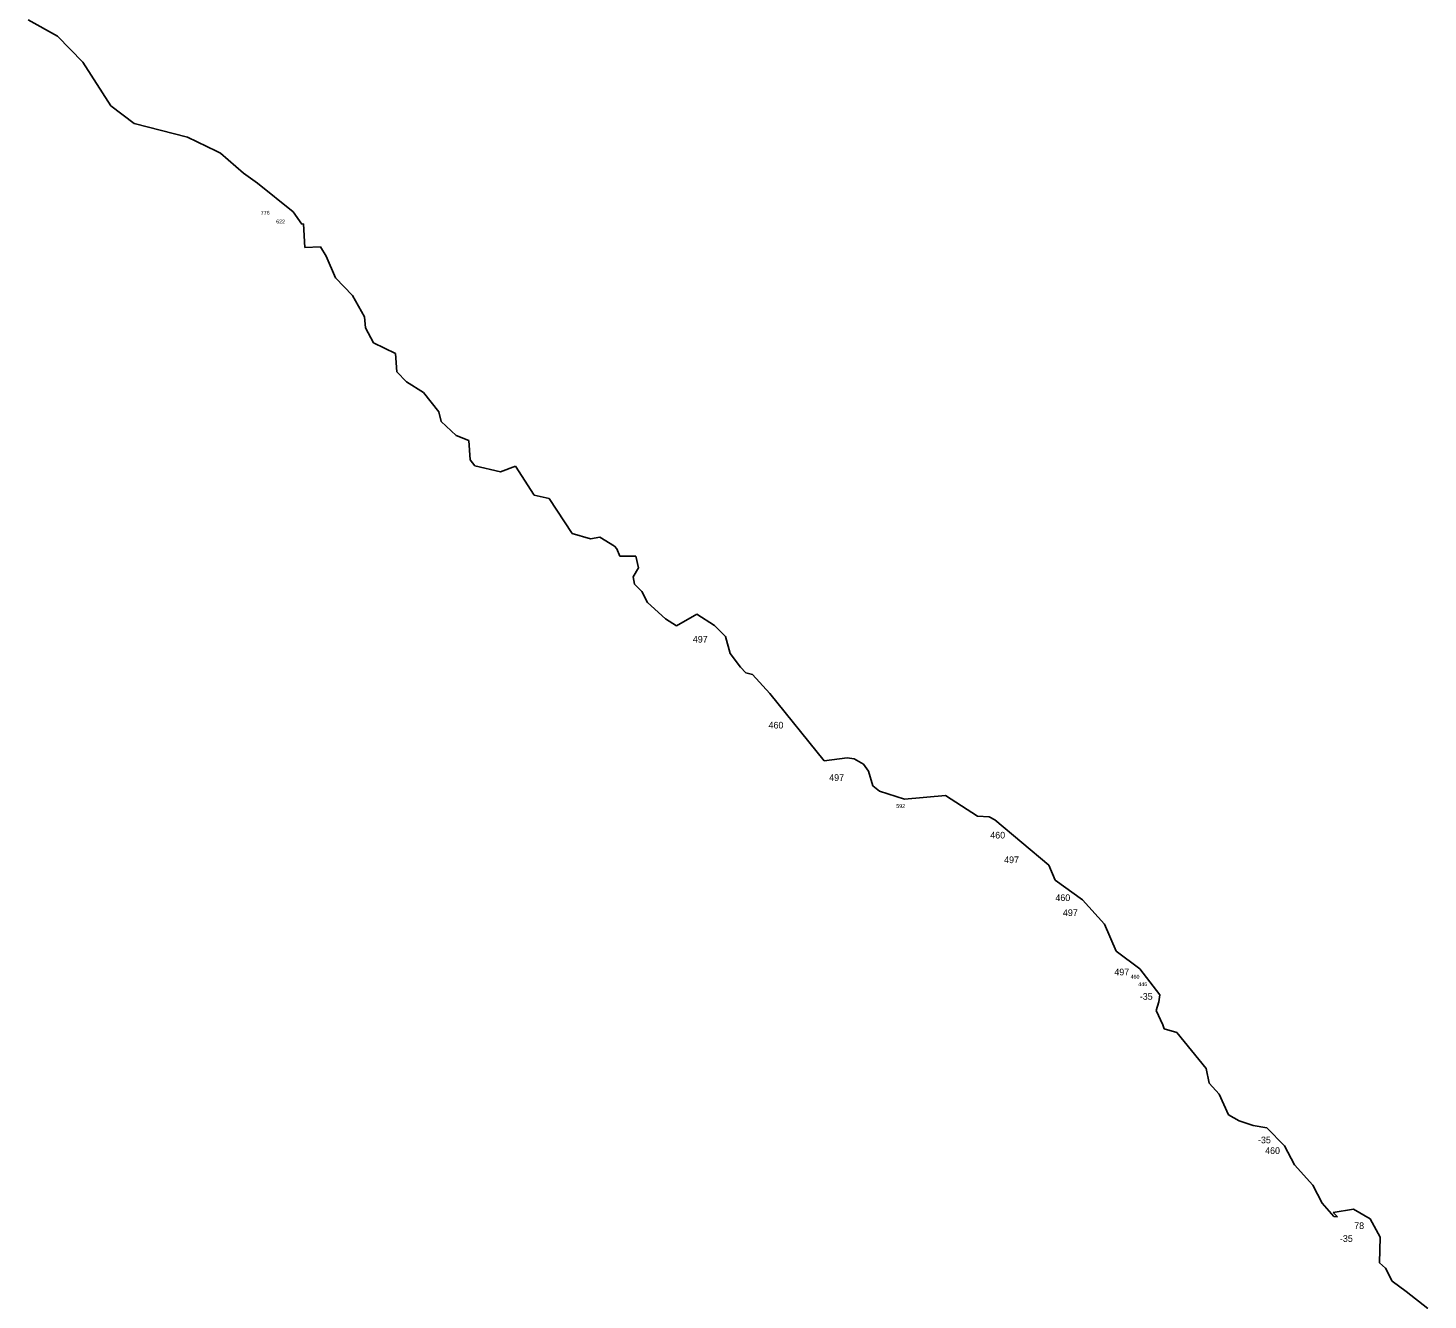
# Model space of a CAD drawing. Extents: x -782977 to -778030, y -975420 to -964838.
# Drawn here: x -779818 to -778366, y -967487 to -966168 of the extents above; entities that cross this region are included whole.
import ezdxf

# ---------------------------------------------------------------- set-up
doc = ezdxf.new("R2010")
doc.units = 0
doc.layers.add('Vrstva 13', color=7, linetype='Continuous')
doc.layers.add('Vrstva 24', color=7, linetype='Continuous')

msp = doc.modelspace()

# ---------------------------------------------------------------- linework, layer by layer
at = {"layer": 'Vrstva 13'}
for p, q in [((-779818.04, -966159.18), (-779787.3, -966176.21)), ((-779787.3, -966176.21), (-779761.3, -966203.24)), ((-779761.3, -966203.24), (-779732.23, -966248.32)), ((-779732.23, -966248.32), (-779707.81, -966266.62)), ((-779707.81, -966266.62), (-779652.48, -966280.84)), ((-779652.48, -966280.84), (-779622.47, -966295.41)), ((-779622.47, -966295.41), (-779618.41, -966297.63)), ((-779618.41, -966297.63), (-779594.6, -966318.31)), ((-779594.6, -966318.31), (-779580.07, -966328.54)), ((-779580.07, -966328.54), (-779543.08, -966358.28)), ((-779543.08, -966358.28), (-779534.09, -966371.21)), ((-779534.09, -966371.21), (-779532.11, -966370.7)), ((-779532.11, -966370.7), (-779530.87, -966395.46)), ((-779530.87, -966395.46), (-779514.66, -966394.59)), ((-779514.66, -966394.59), (-779508.52, -966404.45)), ((-779508.52, -966404.45), (-779499.02, -966426.88)), ((-779499.02, -966426.88), (-779481.49, -966445.22)), ((-779481.49, -966445.22), (-779468.78, -966467.14)), ((-779468.78, -966467.14), (-779467.76, -966478.72)), ((-779467.76, -966478.72), (-779459.43, -966494.18)), ((-779459.43, -966494.18), (-779436.64, -966505.14)), ((-779436.64, -966505.14), (-779435.25, -966524.35)), ((-779435.25, -966524.35), (-779425.39, -966534.65)), ((-779425.39, -966534.65), (-779407.86, -966545.68)), ((-779407.86, -966545.68), (-779391.64, -966565.85)), ((-779391.64, -966565.85), (-779389.3, -966575.94)), ((-779389.3, -966575.94), (-779373.96, -966590.48)), ((-779373.96, -966590.48), (-779360.74, -966595.37)), ((-779360.74, -966595.37), (-779359.28, -966615.68)), ((-779359.28, -966615.68), (-779354.31, -966621.67)), ((-779354.31, -966621.67), (-779327.87, -966628.1)), ((-779327.87, -966628.1), (-779312.09, -966622.11)), ((-779312.09, -966622.11), (-779292.96, -966652.07)), ((-779292.96, -966652.07), (-779277.47, -966655.72)), ((-779277.47, -966655.72), (-779253.37, -966692.03)), ((-779253.37, -966692.03), (-779234.31, -966697.51)), ((-779234.31, -966697.51), (-779224.88, -966695.61)), ((-779224.88, -966695.61), (-779209.4, -966705.12)), ((-779209.4, -966705.12), (-779206.99, -966707.82)), ((-779206.99, -966707.82), (-779203.93, -966715.42)), ((-779203.93, -966715.42), (-779187.35, -966715.42)), ((-779187.35, -966715.42), (-779184.5, -966727.62)), ((-779184.5, -966727.62), (-779190.11, -966736.83)), ((-779190.11, -966736.83), (-779188.95, -966744.43)), ((-779188.95, -966744.43), (-779181.2, -966751.96)), ((-779181.2, -966751.96), (-779175.29, -966763.5)), ((-779175.29, -966763.5), (-779156.74, -966780.38)), ((-779145.24, -966787.65), (-779124.16, -966775.64)), ((-779124.16, -966775.64), (-779105.9, -966787.25)), ((-779156.74, -966780.38), (-779145.24, -966787.65)), ((-779105.9, -966787.25), (-779094.51, -966798.72)), ((-779094.51, -966798.72), (-779089.47, -966816.26)), ((-779089.47, -966816.26), (-779078.66, -966830.58)), ((-779078.66, -966830.58), (-779073.4, -966836.35)), ((-779073.4, -966836.35), (-779066.46, -966838.32)), ((-779066.46, -966838.32), (-779048.33, -966857.77)), ((-779048.33, -966857.77), (-778991.94, -966927.92)), ((-778991.94, -966927.92), (-778968.06, -966924.48)), ((-778960.83, -966925.58), (-778968.06, -966924.48)), ((-778951.06, -966931.24), (-778960.83, -966925.58)), ((-778945.93, -966938.59), (-778951.06, -966931.24)), ((-778941.54, -966953.78), (-778945.93, -966938.59)), ((-778934.53, -966959.34), (-778941.54, -966953.78)), ((-778908.82, -966967.38), (-778934.53, -966959.34)), ((-778908.82, -966967.38), (-778866.02, -966963.57)), ((-778866.02, -966963.57), (-778833.07, -966985.12)), ((-778833.07, -966985.12), (-778820.72, -966985.93)), ((-778820.72, -966985.93), (-778815.02, -966988.86)), ((-778815.02, -966988.86), (-778758.93, -967036.06)), ((-778758.93, -967036.06), (-778752.5, -967051.69)), ((-778752.5, -967051.69), (-778724.15, -967072.01)), ((-778724.15, -967072.01), (-778701.22, -967097.28)), ((-778701.22, -967097.28), (-778689.1, -967125.05)), ((-778689.1, -967125.05), (-778664.56, -967143.32)), ((-778664.56, -967143.32), (-778643.73, -967170.35)), ((-778644.83, -967177.66), (-778647.46, -967186.87)), ((-778643.73, -967170.35), (-778644.83, -967177.66)), ((-778647.46, -967186.87), (-778640.52, -967201.71)), ((-778640.52, -967201.71), (-778639.29, -967205.87)), ((-778639.29, -967205.87), (-778626.21, -967209.6)), ((-778626.21, -967209.6), (-778595.68, -967246.79)), ((-778595.68, -967246.79), (-778592.57, -967262.17)), ((-778592.57, -967262.17), (-778582.24, -967273.46)), ((-778582.24, -967273.46), (-778572.34, -967295.06)), ((-778572.34, -967295.06), (-778561.56, -967301.09)), ((-778561.56, -967301.09), (-778546.81, -967305.84)), ((-778546.81, -967305.84), (-778532.86, -967308.47)), ((-778532.86, -967308.47), (-778514.38, -967326.96)), ((-778514.38, -967326.96), (-778504, -967346.68)), ((-778504, -967346.68), (-778485.02, -967367.88)), ((-778485.02, -967367.88), (-778475.16, -967386.59)), ((-778475.16, -967386.59), (-778463.25, -967400.47)), ((-778442.94, -967392.86), (-778463.83, -967396.08)), ((-778463.83, -967396.08), (-778459.45, -967400.61)), ((-778459.45, -967400.61), (-778463.25, -967400.47)), ((-778425.7, -967402.66), (-778442.94, -967392.86)), ((-778415.33, -967421.8), (-778425.7, -967402.66)), ((-778415.92, -967448.4), (-778415.33, -967421.8)), ((-778409.5, -967454.03), (-778415.92, -967448.4)), ((-778402.71, -967467.54), (-778409.5, -967454.03)), ((-778388.18, -967478.07), (-778402.71, -967467.54)), ((-778365.53, -967495.83), (-778388.18, -967478.07))]:
    msp.add_line(p, q, dxfattribs=at)

# ---------------------------------------------------------------- texts
at = {"layer": 'Vrstva 24'}
for s, height, p in [('776', 4, (-779576.545, -966361.33)), ('622', 4, (-779560.544, -966370.37)), ('497', 6.912, (-779128.268, -966805.122)), ('460', 6.912, (-779049.734, -966894.212)), ('497', 6.912, (-778986.798, -966948.572)), ('592', 4, (-778917.224, -966976.64)), ('460', 6.912, (-778819.684, -967008.302)), ('497', 6.912, (-778805.308, -967033.852)), ('460', 6.912, (-778752.114, -967073.192)), ('497', 6.912, (-778744.298, -967088.702)), ('497', 6.912, (-778690.958, -967150.242)), ('460', 4, (-778674.123, -967153.68)), ('446', 4, (-778666.093, -967161.41)), ('-35', 6.912, (-778664.546, -967175.575)), ('-35', 6.912, (-778541.936, -967324.405)), ('460', 6.912, (-778534.524, -967335.532)), ('78', 6.912, (-778442.103, -967413.392)), ('-35', 6.912, (-778456.926, -967426.665))]:
    msp.add_text(s, height=height, dxfattribs=at).set_placement(p)

doc.saveas('drawing.dxf')
